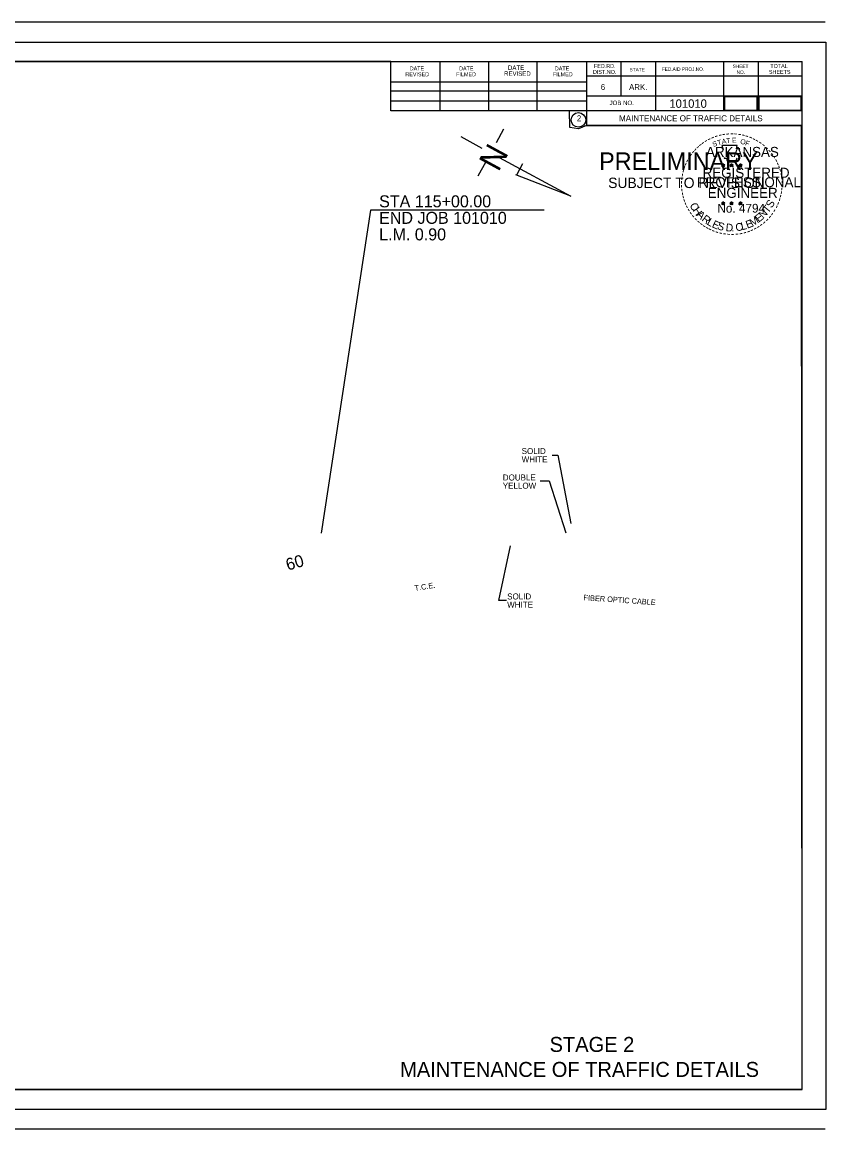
# Model space of a CAD drawing. Extents: x 9844 to 11605, y 9961 to 11323.
# Drawn here: x 10801 to 11605, y 9961 to 11067 of the extents above; entities that cross this region are included whole.
import ezdxf

# ---------------------------------------------------------------- set-up
doc = ezdxf.new("R2010")
doc.units = 0
for name, color, linetype in [('Default', 7, 'Continuous'), ('Page Number', 7, 'Continuous'), ('R_Border', 7, 'Continuous'), ('R_Border Notes', 7, 'Continuous'), ('R_Border Prem', 7, 'Continuous'), ('R_Detour Annot', 7, 'Continuous'), ('R_NoPlot', 7, 'Continuous'), ('R_Stamp', 7, 'Continuous'), ('R_Temp Const Easement Annot', 7, 'Continuous'), ('S_FIBER_OPTIC_CABLE_ANNOT', 7, 'Continuous'), ('STA Text', 7, 'Continuous'), ('TEXT', 7, 'Continuous'), ('Total_Pages', 7, 'Continuous')]:
    doc.layers.add(name, color=color, linetype=linetype)

msp = doc.modelspace()

# ---------------------------------------------------------------- linework, layer by layer
at = {"layer": 'Default'}
for p, q in [((11239.6, 10952.3), (11260.6, 10940.9)), ((11282.3, 10959.6), (11274.9, 10946)), ((11278, 10931.5), (11349.5, 10892.7)), ((11264.6, 10927), (11256.8, 10912.6)), ((11301.4, 10925.2), (11295.2, 10913.8)), ((11349.5, 10892.7), (11294.8, 10914))]:
    msp.add_line(p, q, dxfattribs=at)
at = {"layer": 'Page Number'}
msp.add_lwpolyline([(11503.2, 10978.6), (11535.9, 10978.6), (11535.9, 10991.9), (11503.2, 10991.9)], close=True, dxfattribs=at)
at = {"layer": 'R_Border'}
for p, q in [((11603.9, 11066.7), (9843.9, 11066.7)), ((10000, 11027.3), (11580.9, 11027.3)), ((11169.6, 10977.9), (11169.6, 11027.3)), ((11218.9, 10977.9), (11218.9, 11026.3)), ((11267.7, 10977.9), (11267.7, 11026.3)), ((11316.1, 10977.9), (11316.1, 11026.3)), ((11365.4, 11027.3), (11365.4, 10963.3)), ((11399.6, 11027.3), (11399.6, 10992.6)), ((11434.3, 11027.3), (11434.3, 10977.9)), ((11502.2, 11027.3), (11502.2, 10977.9)), ((11536.9, 11027.3), (11536.9, 10977.9)), ((11580.9, 10000), (11580.9, 11027.3)), ((11169.6, 11007.2), (11365.4, 11007.2)), ((11580.9, 11012.6), (11365.4, 11012.6)), ((11580.9, 11012.7), (11580.9, 11012.7)), ((11169.6, 10997.9), (11365.4, 10997.9)), ((11169.6, 10988.2), (11365.4, 10988.2)), ((11580.9, 10992.6), (11365.4, 10992.6)), ((11580.9, 10977.9), (11169.6, 10977.9)), ((11365.4, 10963.3), (11580.9, 10963.3)), ((11580.9, 10000), (10000, 10000)), ((9843.9, 9960.6), (11603.9, 9960.6))]:
    msp.add_line(p, q, dxfattribs=at)
msp.add_circle((11357.3, 10969), 7.33, dxfattribs=at)
at = {"layer": 'R_NoPlot'}
for points in [[(9938, 11046.8), (11604.7, 11046.8), (11604.7, 9980.1), (9938, 9980.1)], [(10000, 10000), (11580.9, 10000), (11580.3, 10963.3), (11365.4, 10963.3), (11357.3, 10959.9), (11348.5, 10961.4), (11348.3, 10977.9), (11169.6, 10977.9), (11169.6, 11027.3), (10000, 11027.3)], [(10000, 10000), (11580.9, 10000), (11580.3, 10963.3), (11365.4, 10963.3), (11357.3, 10959.9), (11348.5, 10961.4), (11348.3, 10977.9), (11169.6, 10977.9), (11169.6, 11027.3), (10000, 11027.3)], [(10000, 10000), (11580.9, 10000), (11580.3, 10963.3), (11365.4, 10963.3), (11357.3, 10959.9), (11348.5, 10961.4), (11348.3, 10977.9), (11169.6, 10977.9), (11169.6, 11027.3), (10000, 11027.3)]]:
    msp.add_lwpolyline(points, close=True, dxfattribs=at)
at = {"layer": 'R_Stamp'}
for p, q in [((11500.3, 10924), (11502.1, 10923.5)), ((11500.3, 10924), (11501.6, 10923.8)), ((11500.3, 10924), (11501.5, 10923.4)), ((11501, 10922), (11502.1, 10923.5)), ((11501, 10922), (11501.6, 10923.2)), ((11501, 10922), (11502, 10923.1)), ((11502.1, 10925.3), (11501.8, 10924.1)), ((11503.1, 10922), (11502, 10923.1)), ((11502.1, 10923.5), (11502.1, 10925.3)), ((11502.1, 10925.3), (11502.3, 10924.1)), ((11503.8, 10924), (11502.1, 10923.5)), ((11503.1, 10922), (11502.1, 10923.5)), ((11503.8, 10924), (11502.4, 10923.8)), ((11503.1, 10922), (11502.4, 10923.5)), ((11503.8, 10924), (11502.8, 10923.5)), ((11508.7, 10924), (11510.4, 10923.5)), ((11508.7, 10924), (11509.9, 10923.8)), ((11508.7, 10924), (11509.8, 10923.4)), ((11509.3, 10922), (11510.4, 10923.5)), ((11509.3, 10922), (11510, 10923.2)), ((11509.3, 10922), (11510.4, 10923.1)), ((11510.4, 10925.3), (11510.2, 10924.1)), ((11510.4, 10923.5), (11510.4, 10925.3)), ((11510.4, 10925.3), (11510.6, 10924.1)), ((11512.1, 10924), (11510.4, 10923.5)), ((11511.5, 10922), (11510.4, 10923.5)), ((11511.5, 10922), (11510.4, 10923.1)), ((11512.1, 10924), (11510.7, 10923.8)), ((11511.5, 10922), (11510.8, 10923.5)), ((11512.1, 10924), (11511.1, 10923.5)), ((11517.5, 10924), (11519.2, 10923.4)), ((11517.5, 10924), (11518.7, 10923.8)), ((11517.5, 10924), (11518.7, 10923.4)), ((11518.1, 10921.9), (11519.2, 10923.4)), ((11518.1, 10921.9), (11518.8, 10923.2)), ((11518.1, 10921.9), (11519.2, 10923)), ((11519.2, 10925.3), (11519, 10924)), ((11519.2, 10923.4), (11519.2, 10925.3)), ((11519.2, 10925.3), (11519.5, 10924)), ((11521, 10924), (11519.2, 10923.4)), ((11520.3, 10921.9), (11519.2, 10923.4)), ((11520.3, 10921.9), (11519.2, 10923)), ((11521, 10924), (11519.5, 10923.7)), ((11520.3, 10921.9), (11519.6, 10923.4)), ((11521, 10924), (11519.9, 10923.5)), ((11500.3, 10886.2), (11502, 10885.6)), ((11500.3, 10886.2), (11501.6, 10886)), ((11500.3, 10886.2), (11501.5, 10885.6)), ((11501, 10884.1), (11502, 10885.6)), ((11501, 10884.1), (11501.6, 10885.4)), ((11501, 10884.1), (11502, 10885.2)), ((11502, 10887.4), (11501.8, 10886.2)), ((11502, 10885.6), (11502, 10887.4)), ((11502, 10887.4), (11502.3, 10886.2)), ((11503.8, 10886.2), (11502, 10885.6)), ((11503.1, 10884.1), (11502, 10885.6)), ((11503.1, 10884.1), (11502, 10885.2)), ((11503.8, 10886.2), (11502.3, 10885.9)), ((11503.1, 10884.1), (11502.4, 10885.6)), ((11503.8, 10886.2), (11502.7, 10885.7)), ((11508.6, 10886.2), (11510.4, 10885.6)), ((11508.6, 10886.2), (11509.9, 10886)), ((11508.6, 10886.2), (11509.8, 10885.6)), ((11509.3, 10884.1), (11510.4, 10885.6)), ((11509.3, 10884.1), (11509.9, 10885.4)), ((11509.3, 10884.1), (11510.4, 10885.2)), ((11510.4, 10887.4), (11510.2, 10886.2)), ((11510.4, 10885.6), (11510.4, 10887.4)), ((11510.4, 10887.4), (11510.6, 10886.2)), ((11512.1, 10886.2), (11510.4, 10885.6)), ((11511.4, 10884.1), (11510.4, 10885.6)), ((11511.4, 10884.1), (11510.4, 10885.2)), ((11512.1, 10886.2), (11510.7, 10885.9)), ((11511.4, 10884.1), (11510.8, 10885.6)), ((11512.1, 10886.2), (11511.1, 10885.7)), ((11517.5, 10886.1), (11519.2, 10885.6)), ((11517.5, 10886.1), (11518.7, 10885.9)), ((11517.5, 10886.1), (11518.7, 10885.5)), ((11518.1, 10884.1), (11519.2, 10885.6)), ((11518.1, 10884.1), (11518.8, 10885.3)), ((11518.1, 10884.1), (11519.2, 10885.2)), ((11519.2, 10887.4), (11519, 10886.1)), ((11519.2, 10885.6), (11519.2, 10887.4)), ((11519.2, 10887.4), (11519.5, 10886.1)), ((11520.9, 10886.1), (11519.2, 10885.6)), ((11520.3, 10884.1), (11519.2, 10885.6)), ((11520.3, 10884.1), (11519.2, 10885.2)), ((11520.9, 10886.1), (11519.5, 10885.9)), ((11520.3, 10884.1), (11519.6, 10885.5)), ((11520.9, 10886.1), (11519.9, 10885.6))]:
    msp.add_line(p, q, dxfattribs=at)
for points in [[(11500.5, 10943.4), (11501.9, 10939.3)], [(11518.1, 10938.8), (11518.8, 10940.2), (11515.4, 10940.1), (11516.1, 10943.4), (11500.5, 10943.4)], [(11503, 10931.3), (11503, 10930.9), (11505.8, 10930.8), (11505.5, 10928.4), (11514.9, 10928.4), (11515.9, 10931.1)], [(11502.1, 10925.3), (11503.1, 10922), (11500.3, 10924), (11503.8, 10924), (11501, 10922), (11502.1, 10925.3)], [(11510.4, 10925.3), (11511.5, 10922), (11508.7, 10924), (11512.1, 10924), (11509.3, 10922), (11510.4, 10925.3)], [(11519.2, 10925.3), (11520.3, 10921.9), (11517.5, 10924), (11521, 10924), (11518.1, 10921.9), (11519.2, 10925.3)], [(11502, 10887.4), (11503.1, 10884.1), (11500.3, 10886.2), (11503.8, 10886.2), (11501, 10884.1), (11502, 10887.4)], [(11510.4, 10887.4), (11511.4, 10884.1), (11508.6, 10886.2), (11512.1, 10886.2), (11509.3, 10884.1), (11510.4, 10887.4)], [(11519.2, 10887.4), (11520.3, 10884.1), (11517.5, 10886.1), (11520.9, 10886.1), (11518.1, 10884.1), (11519.2, 10887.4)]]:
    msp.add_lwpolyline(points, dxfattribs=at)
for centre, radius in [((11502, 10923.5), 0.861), ((11502, 10923.5), 0.723), ((11502, 10923.5), 0.579), ((11502, 10923.5), 0.495), ((11502, 10923.5), 0.374), ((11502, 10923.5), 0.248), ((11502, 10923.5), 0.148), ((11510.4, 10923.5), 0.861), ((11510.4, 10923.5), 0.723), ((11510.4, 10923.5), 0.579), ((11510.4, 10923.5), 0.495), ((11510.4, 10923.5), 0.374), ((11510.4, 10923.5), 0.248), ((11510.4, 10923.5), 0.148), ((11519.2, 10923.4), 0.861), ((11519.2, 10923.4), 0.723), ((11519.2, 10923.4), 0.579), ((11519.2, 10923.4), 0.495), ((11519.2, 10923.4), 0.374), ((11519.2, 10923.4), 0.248), ((11519.2, 10923.4), 0.148), ((11502, 10885.6), 0.861), ((11502, 10885.6), 0.723), ((11502, 10885.6), 0.579), ((11502, 10885.6), 0.495), ((11502, 10885.6), 0.374), ((11502, 10885.6), 0.248), ((11502, 10885.6), 0.148), ((11510.4, 10885.6), 0.861), ((11510.4, 10885.6), 0.723), ((11510.4, 10885.6), 0.579), ((11510.4, 10885.6), 0.495), ((11510.4, 10885.6), 0.374), ((11510.4, 10885.6), 0.248), ((11510.4, 10885.6), 0.148), ((11519.2, 10885.6), 0.861), ((11519.2, 10885.6), 0.723), ((11519.2, 10885.6), 0.579), ((11519.2, 10885.6), 0.495), ((11519.2, 10885.6), 0.374), ((11519.2, 10885.6), 0.248), ((11519.2, 10885.6), 0.148)]:
    msp.add_circle(centre, radius, dxfattribs=at)
at = {"layer": 'STA Text'}
msp.add_lwpolyline([(11322.9, 10878.8), (11149.5, 10878.8), (11100, 10555.8)], dxfattribs=at)
at = {"layer": 'TEXT'}
for points in [[(11330.9, 10633.9), (11336.7, 10633.9), (11349.7, 10565.6)], [(11319.1, 10608.2), (11328, 10608.2), (11344.6, 10556.2)], [(11285.3, 10488.8), (11277.6, 10488.8), (11289.3, 10543.3)]]:
    msp.add_lwpolyline(points, dxfattribs=at)
at = {"layer": 'Total_Pages'}
msp.add_lwpolyline([(11537.7, 10978.6), (11580.1, 10978.6), (11580.1, 10991.9), (11537.7, 10991.9)], close=True, dxfattribs=at)

# ---------------------------------------------------------------- texts
at = {"layer": 'Default'}
msp.add_text('N', height=23.3, rotation=241.4896, dxfattribs=at).set_placement((11267.5, 10947.2))
at = {"layer": 'R_Border'}
for s, height, p in [('DATE', 3.91, (11188.6, 11018.5)), ('DATE', 3.91, (11237.9, 11018.5)), ('REVISED', 4.4, (11282.9, 11013.1)), ('DATE', 4.4, (11286.8, 11019)), ('DATE', 3.91, (11333.7, 11018.5)), ('DIST.NO.', 3.91, (11371.8, 11015)), ('FED.RD.', 3.91, (11372.8, 11020.9)), ('STATE', 3.42, (11408.4, 11017.5)), ('FED.AID PROJ.NO.', 3.42, (11440.7, 11018)), ('SHEET', 3.42, (11511.5, 11020.9)), ('NO.', 3.42, (11515.4, 11015)), ('SHEETS', 3.91, (11547.7, 11015)), ('TOTAL', 3.91, (11549.1, 11020.9)), ('REVISED', 3.91, (11184.2, 11012.6)), ('FILMED', 3.91, (11235, 11012.6)), ('FILMED', 3.91, (11331.7, 11012.6)), ('6', 5.86, (11379.6, 10998.9)), ('ARK.', 5.86, (11407.9, 10998.9)), ('JOB NO.', 4.4, (11388.4, 10983.8)), ('2', 5.86, (11355.7, 10967.7)), ('STAGE 2', 15, (11328.4, 10037.5)), ('MAINTENANCE OF TRAFFIC DETAILS', 15, (11179, 10012.5))]:
    msp.add_text(s, height=height, dxfattribs=at).set_placement(p)
at = {"layer": 'R_Border Notes'}
for s, height, p in [('101010', 8.4, (11448.2, 10981.1)), ('MAINTENANCE OF TRAFFIC DETAILS', 6, (11397.9, 10967.6))]:
    msp.add_text(s, height=height, dxfattribs=at).set_placement(p)
at = {"layer": 'R_Border Prem'}
for s, height, p in [('PRELIMINARY', 17.5, (11377.9, 10919)), ('SUBJECT TO REVISION', 10.376, (11387, 10900.9))]:
    msp.add_text(s, height=height, dxfattribs=at).set_placement(p)
at = {"layer": 'R_Detour Annot'}
msp.add_text('60', height=12, rotation=16.1937, dxfattribs=at).set_placement((11066.7, 10518.4))
at = {"layer": 'R_Stamp'}
for s, height, rotation, p in [('-', 8, 28.7918, (11487.9, 10946.1)), ('-', 8, 24.3072, (11491.1, 10947.7)), ('-', 8, 19.1761, (11494.3, 10949.1)), ('-', 8, 13.6302, (11498, 10950.3)), ('-', 8, 10.2193, (11501.4, 10951.1)), ('T', 5, 6.0228, (11505.2, 10945.6)), ('-', 8, 5.8968, (11505, 10951.6)), ('-', 8, 0.1862, (11508.9, 10952)), ('E', 5, 0.8323, (11510.8, 10946.1)), ('-', 8, 357.743, (11512.5, 10951.9)), ('-', 8, 352.1617, (11516.2, 10951.6)), ('-', 8, 347.2049, (11519.8, 10951.1)), ('-', 8, 342.3362, (11523, 10950.3)), ('-', 8, 337.8551, (11526.7, 10949.2)), ('-', 8, 334.1211, (11529.8, 10947.8)), ('-', 8, 48.4231, (11475.3, 10935.9)), ('-', 8, 42.9622, (11477.5, 10938.3)), ('-', 8, 38.9507, (11479.7, 10940.4)), ('-', 8, 36.2317, (11482, 10942.3)), ('-', 8, 34.0636, (11484.9, 10944.3)), ('S', 5, 21.594, (11492.3, 10941.8)), ('T', 5, 16.4036, (11496.9, 10943.5)), ('A', 5, 11.2132, (11501, 10944.7)), ('O', 5, 350.4515, (11518.8, 10945.1)), ('F', 5, 340.0707, (11523.5, 10943.9)), ('-', 8, 329.6409, (11532.7, 10946.4)), ('-', 8, 325.8627, (11535.9, 10944.6)), ('-', 8, 320.5297, (11539, 10942.5)), ('-', 8, 315.5786, (11542, 10940)), ('-', 8, 62.8713, (11468, 10925)), ('-', 8, 58.0706, (11469.6, 10928)), ('-', 8, 54.2325, (11471.2, 10930.7)), ('-', 8, 50.6142, (11473.2, 10933.5)), ('-', 8, 309.8797, (11544.8, 10937.3)), ('-', 8, 306.6522, (11547.5, 10934.3)), ('-', 7, 303.6753, (11549.9, 10931.4)), ('-', 8, 299.6684, (11551.5, 10928.4)), ('-', 8, 75.461, (11464.6, 10915.2)), ('-', 8, 72.3945, (11465.6, 10918.8)), ('-', 8, 67.7743, (11466.7, 10921.9)), ('-', 8, 294.6628, (11553.1, 10925.3)), ('-', 8, 290.5728, (11554.4, 10922.5)), ('-', 8, 285.1233, (11555.6, 10919.6)), ('-', 8, 89.0622, (11463.4, 10904.7)), ('-', 8, 85.1863, (11463.6, 10908.2)), ('-', 8, 81.2013, (11464, 10911.6)), ('-', 8, 280.5493, (11556.6, 10915.9)), ('-', 8, 276.5962, (11557.4, 10912)), ('-', 8, 274.3301, (11557.7, 10908.4)), ('-', 8, 94.1959, (11463.6, 10901.1)), ('-', 8, 98.9479, (11464, 10897.7)), ('-', 8, 101.7149, (11464.7, 10894.1)), ('-', 8, 260.9953, (11557.4, 10898.6)), ('-', 8, 263.5172, (11557.7, 10901.9)), ('-', 8, 269.9407, (11557.8, 10905.2)), ('-', 8, 105.4578, (11465.5, 10891.1)), ('-', 8, 109.0874, (11466.5, 10887.9)), ('-', 8, 114.0643, (11467.8, 10884.9)), ('C', 7.7, 296.9133, (11468.2, 10883.9)), ('T', 7.7, 51.5114, (11546.8, 10875.1)), ('S', 7.7, 57.878, (11550.5, 10880.3)), ('-', 8, 247.8887, (11554.8, 10888.3)), ('-', 8, 255.7626, (11555.9, 10891.8)), ('-', 8, 255.7626, (11556.8, 10895.3)), ('-', 8, 115.7289, (11469.3, 10881.9)), ('-', 8, 120.4471, (11471.1, 10878.9)), ('-', 8, 125.8934, (11473.1, 10876.1)), ('-', 8, 130.7181, (11475.4, 10873.4)), ('H', 7.7, 303.2799, (11471.1, 10878.7)), ('A', 7.7, 316.013, (11474.8, 10873.6)), ('R', 7.7, 322.3796, (11479.9, 10868.7)), ('E', 7.7, 38.7783, (11537.6, 10866.2)), ('N', 7.7, 45.1449, (11542, 10869.9)), ('-', 8, 231.2538, (11547.4, 10875.3)), ('-', 8, 233.8452, (11549.5, 10878.1)), ('-', 8, 239.0712, (11551.5, 10881.4)), ('-', 8, 244.6197, (11553.5, 10885.1)), ('-', 8, 134.2238, (11478, 10870.6)), ('-', 8, 138.9338, (11480.7, 10868.3)), ('-', 8, 144.6463, (11483.4, 10866.3)), ('-', 8, 148.0898, (11486.2, 10864.4)), ('-', 8, 151.5704, (11489.1, 10862.8)), ('L', 7.7, 328.7461, (11485, 10864.9)), ('E', 7.7, 335.1127, (11490.1, 10862.1)), ('S', 7.7, 341.4792, (11495.4, 10860)), ('D', 7.7, 354.2124, (11504.2, 10857.9)), ('C', 7.7, 6.9455, (11514.7, 10857.7)), ('L', 7.7, 13.3121, (11520.6, 10858.7)), ('E', 7.7, 19.6786, (11526.1, 10860.3)), ('M', 7.7, 32.4117, (11531.2, 10862.1)), ('-', 8, 212.2491, (11537, 10865.6)), ('-', 8, 215.7363, (11539.6, 10867.6)), ('-', 8, 221.0851, (11542.4, 10869.9)), ('-', 8, 225.7653, (11545, 10872.5)), ('-', 8, 154.6002, (11491.7, 10861.6)), ('-', 8, 158.5612, (11494.9, 10860.3)), ('-', 8, 162.7983, (11498.3, 10859.2)), ('-', 8, 167.5555, (11501.9, 10858.4)), ('-', 8, 173.1155, (11505.7, 10857.9)), ('-', 8, 176.5183, (11509.5, 10857.6)), ('-', 8, 181.5918, (11513.2, 10857.7)), ('.', 7.7, 0.5789, (11510.1, 10857.5)), ('-', 8, 185.8167, (11517.2, 10858.1)), ('-', 8, 191.2858, (11520.9, 10858.7)), ('-', 8, 195.4743, (11524.6, 10859.7)), ('-', 8, 200.7184, (11528, 10860.9)), ('-', 8, 204.2516, (11531, 10862.3)), ('-', 8, 207.3568, (11534.2, 10863.9))]:
    msp.add_text(s, height=height, rotation=rotation, dxfattribs=at).set_placement(p)
for s, height, p in [('ARKANSAS', 10, (11484.8, 10932)), ('REGISTERED', 10, (11481.4, 10911.2)), ('PROFESSIONAL', 10, (11475.6, 10901.7)), ('ENGINEER', 10, (11486.6, 10891.1)), ('No. 4794', 8.78, (11496.2, 10876.3))]:
    msp.add_text(s, height=height, dxfattribs=at).set_placement(p)
at = {"layer": 'R_Temp Const Easement Annot'}
msp.add_text('T.C.E.', height=5.5, rotation=8.9375, dxfattribs=at).set_placement((11193.9, 10498.2))
at = {"layer": 'S_FIBER_OPTIC_CABLE_ANNOT'}
msp.add_text('FIBER OPTIC CABLE', height=5.5, rotation=356.029, dxfattribs=at).set_placement((11362.2, 10489))
at = {"layer": 'STA Text'}
for s, p in [('STA 115+00.00', (11158, 10881.6)), ('END JOB 101010', (11158, 10865.1)), ('L.M. 0.90', (11158, 10848.6))]:
    msp.add_text(s, height=12, dxfattribs=at).set_placement(p)
at = {"layer": 'TEXT'}
for s, p in [('SOLID', (11300.5, 10635)), ('WHITE', (11300.5, 10626.8)), ('DOUBLE', (11281.6, 10608.6)), ('YELLOW', (11281.6, 10600.4)), ('WHITE', (11286, 10481.5)), ('SOLID', (11286, 10489.7))]:
    msp.add_text(s, height=6, rotation=360, dxfattribs=at).set_placement(p)

doc.saveas('drawing.dxf')
